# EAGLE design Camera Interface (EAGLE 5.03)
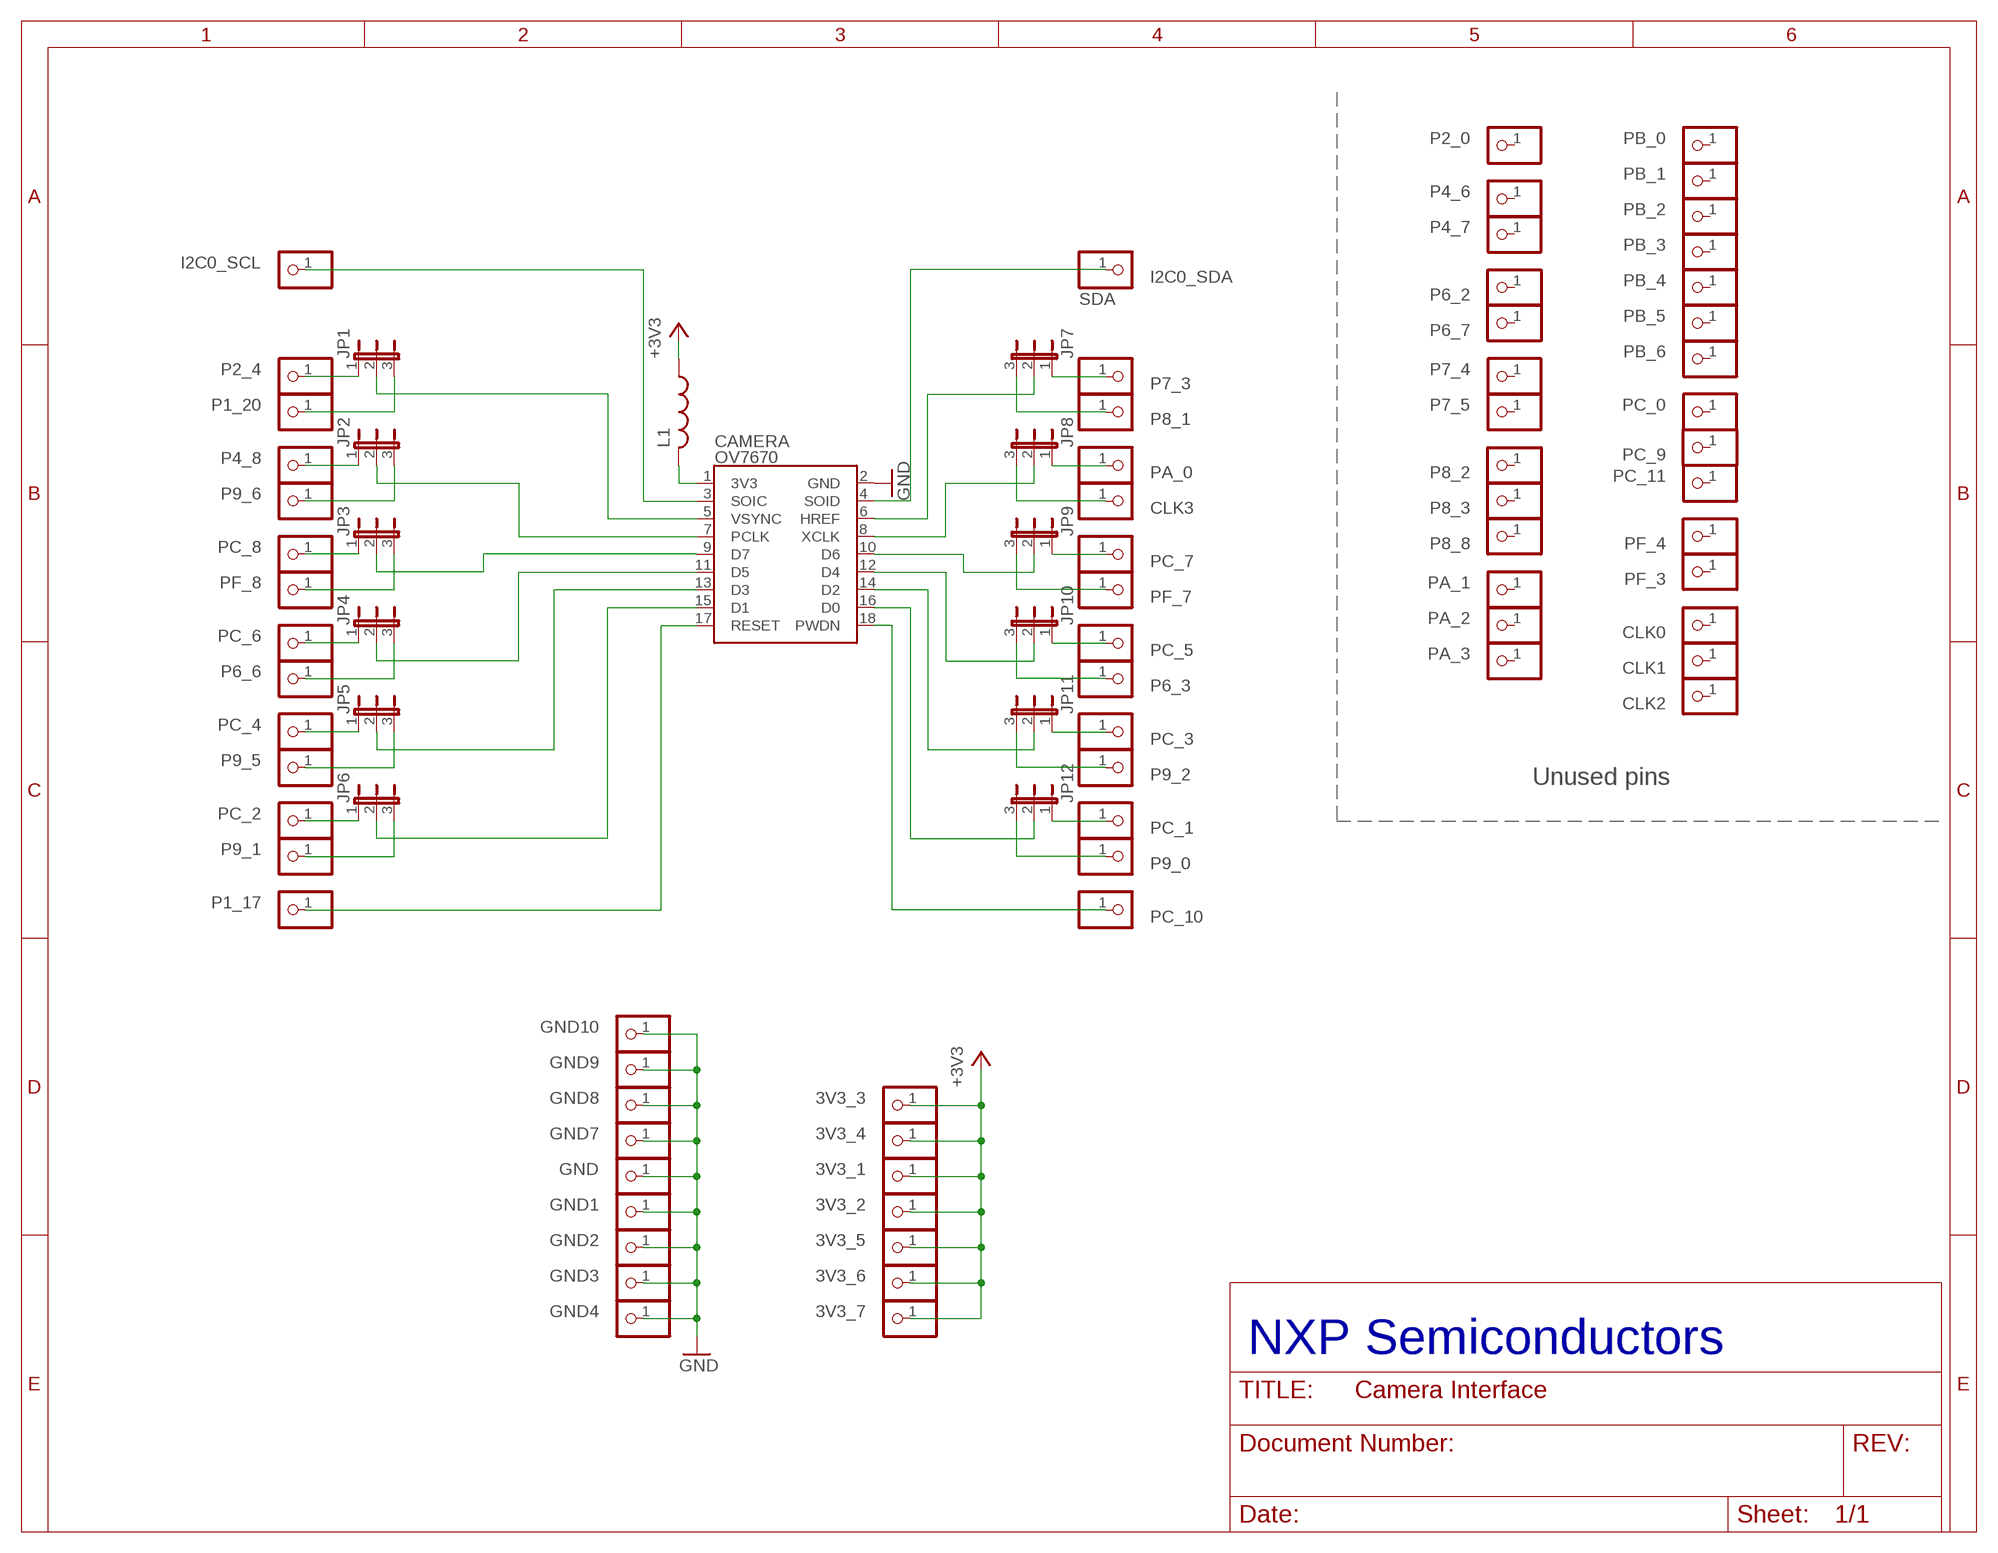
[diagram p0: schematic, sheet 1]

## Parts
3V3_1  PINHD-1X1NS  [1X01NS]
3V3_2  3V3  PINHD-1X1NS  [1X01NS]
3V3_3  3V3  PINHD-1X1NS  [1X01NS]
3V3_4  PINHD-1X1NS  [1X01NS]
3V3_5  3V3  PINHD-1X1NS  [1X01NS]
3V3_6  3V3  PINHD-1X1NS  [1X01NS]
3V3_7  3V3  PINHD-1X1NS  [1X01NS]
CAMERA  OV7670  [2X09]
CLK0  PINHD-1X1SQ  [1X1SQ]
CLK1  PINHD-1X1NS  [1X01NS]
CLK2  PINHD-1X1NS  [1X01NS]
CLK3  PINHD-1X1NS  [1X01NS]
GND  PINHD-1X1SQ  [1X1SQ]
GND1  PINHD-1X1NS  [1X01NS]
GND2  PINHD-1X1SQ  [1X1SQ]
GND3  PINHD-1X1NS  [1X01NS]
GND4  GND  PINHD-1X1NS  [1X01NS]
GND7  GND  PINHD-1X1NS  [1X01NS]
GND8  GND  PINHD-1X1NS  [1X01NS]
GND9  GND  PINHD-1X1NS  [1X01NS]
GND10  GND  PINHD-1X1NS  [1X01NS]
I2C0_SCL  PINHD-1X1NS  [1X01NS]
I2C0_SDA  SDA  PINHD-1X1NS  [1X01NS]
JP1  JP2ENS  [JP2S_NS]
JP2  JP2ENS  [JP2S_NS]
JP3  JP2ENS  [JP2S_NS]
JP4  JP2ENS  [JP2S_NS]
JP5  JP2ENS  [JP2S_NS]
JP6  JP2ENS  [JP2S_NS]
JP7  JP2ENS  [JP2S_NS]
JP8  JP2ENS  [JP2S_NS]
JP9  JP2ENS  [JP2S_NS]
JP10  JP2ENS  [JP2S_NS]
JP11  JP2ENS  [JP2S_NS]
JP12  JP2ENS  [JP2S_NS]
L1  L-USL0805  [C0805]
P1_17  PINHD-1X1NS  [1X01NS]
P1_20  PINHD-1X1NS  [1X01NS]
P2_0  PINHD-1X1NS  [1X01NS]
P2_4  PINHD-1X1NS  [1X01NS]
P4_6  PINHD-1X1NS  [1X01NS]
P4_7  PINHD-1X1NS  [1X01NS]
P4_8  PINHD-1X1NS  [1X01NS]
P6_2  PINHD-1X1NS  [1X01NS]
P6_3  PINHD-1X1NS  [1X01NS]
P6_6  PINHD-1X1NS  [1X01NS]
P6_7  PINHD-1X1NS  [1X01NS]
P7_3  PINHD-1X1NS  [1X01NS]
P7_4  PINHD-1X1NS  [1X01NS]
P7_5  PINHD-1X1NS  [1X01NS]
P8_1  PINHD-1X1NS  [1X01NS]
P8_2  PINHD-1X1NS  [1X01NS]
P8_3  PINHD-1X1NS  [1X01NS]
P8_8  PINHD-1X1NS  [1X01NS]
P9_0  PINHD-1X1SQ  [1X1SQ]
P9_1  PINHD-1X1NS  [1X01NS]
P9_2  PINHD-1X1NS  [1X01NS]
P9_5  PINHD-1X1NS  [1X01NS]
P9_6  PINHD-1X1NS  [1X01NS]
PA_0  PINHD-1X1SQ  [1X1SQ]
PA_1  PINHD-1X1NS  [1X01NS]
PA_2  PINHD-1X1NS  [1X01NS]
PA_3  PINHD-1X1NS  [1X01NS]
PB_0  PINHD-1X1SQ  [1X1SQ]
PB_1  PINHD-1X1NS  [1X01NS]
PB_2  PINHD-1X1NS  [1X01NS]
PB_3  PINHD-1X1NS  [1X01NS]
PB_4  PINHD-1X1NS  [1X01NS]
PB_5  PINHD-1X1NS  [1X01NS]
PB_6  PINHD-1X1NS  [1X01NS]
PC_0  PINHD-1X1SQ  [1X1SQ]
PC_1  PINHD-1X1NS  [1X01NS]
PC_2  PINHD-1X1NS  [1X01NS]
PC_3  PINHD-1X1NS  [1X01NS]
PC_4  PINHD-1X1NS  [1X01NS]
PC_5  PINHD-1X1NS  [1X01NS]
PC_6  PINHD-1X1NS  [1X01NS]
PC_7  PINHD-1X1NS  [1X01NS]
PC_8  PINHD-1X1NS  [1X01NS]
PC_9  PINHD-1X1NS  [1X01NS]
PC_10  PINHD-1X1NS  [1X01NS]
PC_11  PINHD-1X1NS  [1X01NS]
PF_3  PINHD-1X1NS  [1X01NS]
PF_4  PINHD-1X1NS  [1X01NS]
PF_7  PINHD-1X1NS  [1X01NS]
PF_8  PINHD-1X1NS  [1X01NS]

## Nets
+3V3: 3V3_1.1 3V3_2.1 3V3_3.1 3V3_4.1 3V3_5.1 3V3_6.1 3V3_7.1 L1.1
D0: CAMERA.16(D0) JP12.2
D1: CAMERA.15(D1) JP6.2
D2: CAMERA.14(D2) JP11.2
D3: CAMERA.13(D3) JP5.2
D4: CAMERA.12(D4) JP10.2
D5: CAMERA.11(D5) JP4.2
D6: CAMERA.10(D6) JP9.2
D7: CAMERA.9(D7) JP3.2
GND: CAMERA.2(GND) GND1.1 GND2.1 GND3.1 GND4.1 GND7.1 GND8.1 GND9.1 GND10.1 GND.1
HREF: CAMERA.6(HREF) JP7.2
N$3: JP1.1 P2_4.1
N$4: JP7.1 P7_3.1
N$6: JP8.1 PA_0.1
N$7: JP3.1 PC_8.1
N$8: JP9.1 PC_7.1
N$10: JP10.1 PC_5.1
N$12: JP11.1 PC_3.1
N$14: JP12.1 PC_1.1
N$17: JP1.3 P1_20.1
N$19: JP2.1 P4_8.1
N$20: JP2.3 P9_6.1
N$21: JP3.3 PF_8.1
N$23: JP4.1 PC_6.1
N$24: JP4.3 P6_6.1
N$25: JP5.1 PC_4.1
N$26: JP5.3 P9_5.1
N$27: JP6.1 PC_2.1
N$28: JP6.3 P9_1.1
N$29: JP7.3 P8_1.1
N$30: CLK3.1 JP8.3
N$31: JP9.3 PF_7.1
N$32: JP10.3 P6_3.1
N$33: JP11.3 P9_2.1
N$34: JP12.3 P9_0.1
N$41: CAMERA.1(3V3) L1.2
PCLK: CAMERA.7(PCLK) JP2.2
PWDN: CAMERA.18(PWDN) PC_10.1
RESET: CAMERA.17(RESET) P1_17.1
SCL: CAMERA.3(SOIC) I2C0_SCL.1
SDA: CAMERA.4(SOID) I2C0_SDA.1
VSYNC: CAMERA.5(VSYNC) JP1.2
XCLK: CAMERA.8(XCLK) JP8.2
Unconnected: CLK0.1 CLK1.1 CLK2.1 P2_0.1 P4_6.1 P4_7.1 P6_2.1 P6_7.1 P7_4.1 P7_5.1 P8_2.1 P8_3.1 P8_8.1 PA_1.1 PA_2.1 PA_3.1 PB_0.1 PB_1.1 PB_2.1 PB_3.1 PB_4.1 PB_5.1 PB_6.1 PC_0.1 PC_9.1 PC_11.1 PF_3.1 PF_4.1

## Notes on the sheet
- Unused pins
- NXP Semiconductors

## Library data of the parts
3V3_1-3V3_7 CLK0 CLK1-CLK3 GND GND1-GND4 GND7-GND10 I2C0_SCL I2C0_SDA P1_17 P1_20 P2_0 P2_4 P4_6-P4_8 P6_2 P6_3 P6_6 P6_7 P7_3-P7_5 P8_1-P8_3 P8_8 P9_0 P9_1 P9_2 P9_5 P9_6 PA_0 PA_1-PA_3 PB_0 PB_1-PB_6 PC_0 PC_1-PC_11 PF_3 PF_4 PF_7 PF_8 = pinhead:PINHD-1X1: PIN HEADER
CAMERA = Camera_Interface:OV7670
JP1-JP12 = jumper:JP2E: JUMPER
L1 = rcl:L-US: INDUCTOR, American symbol

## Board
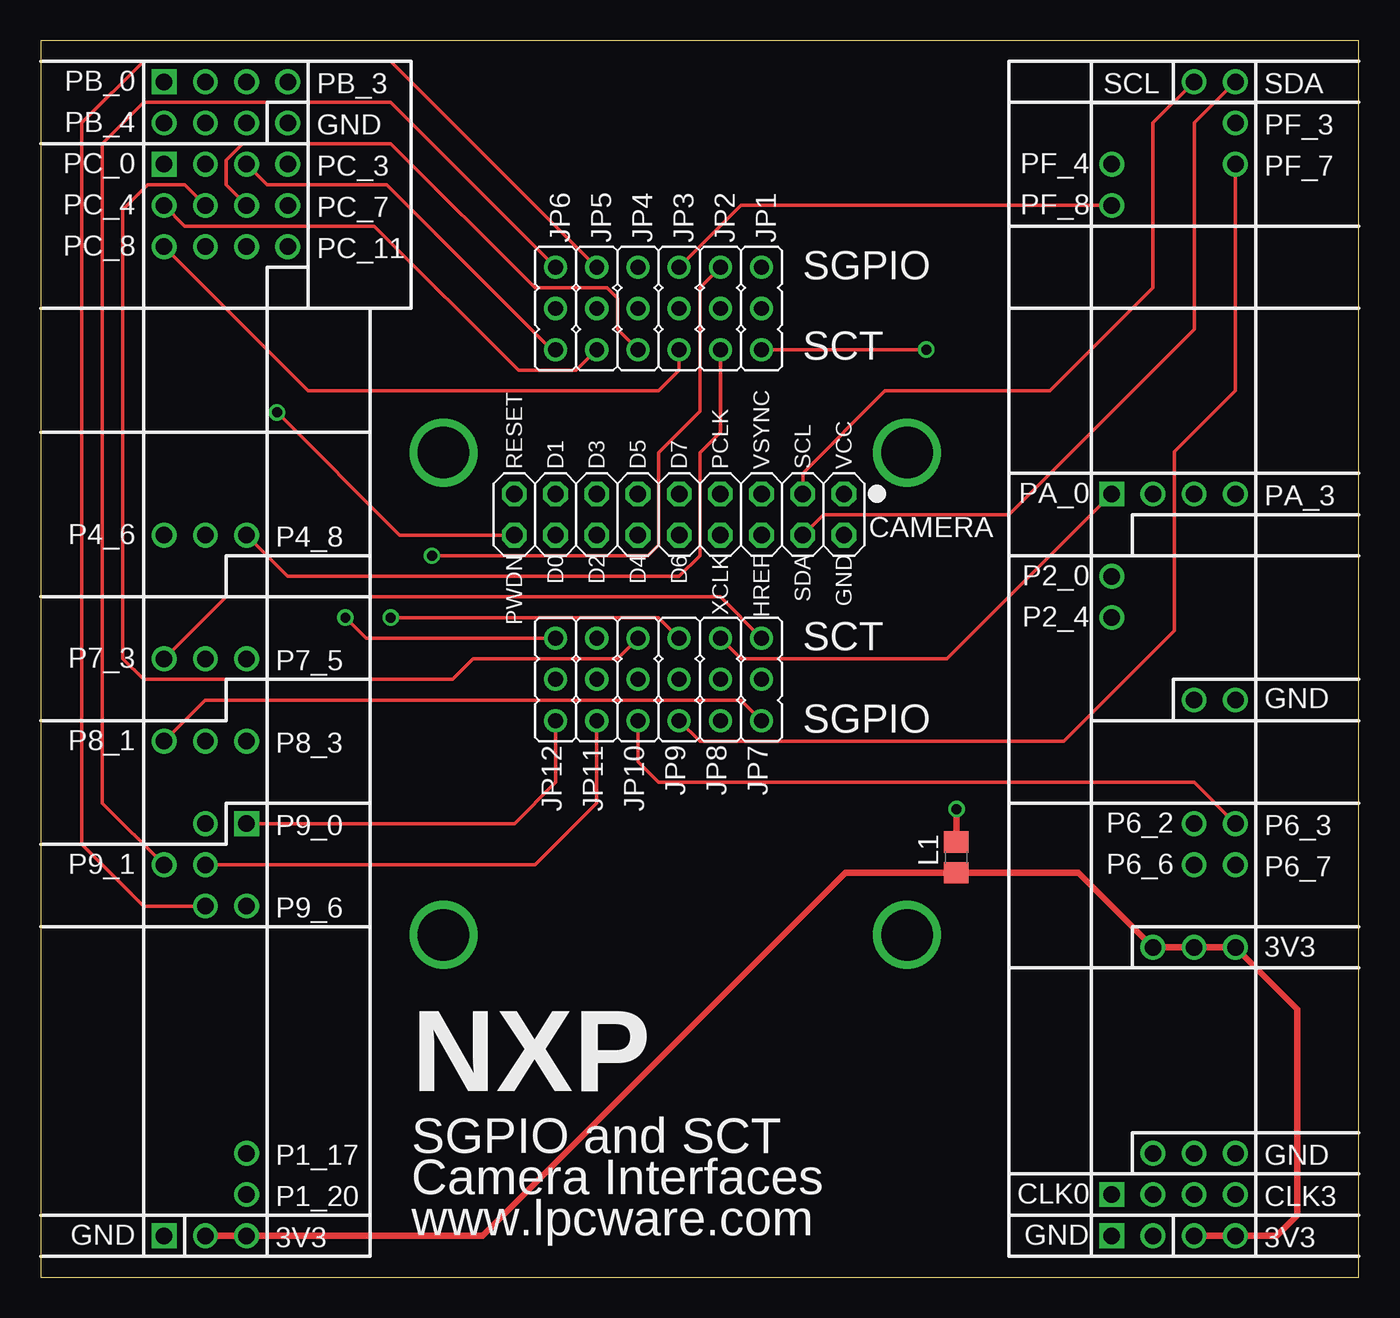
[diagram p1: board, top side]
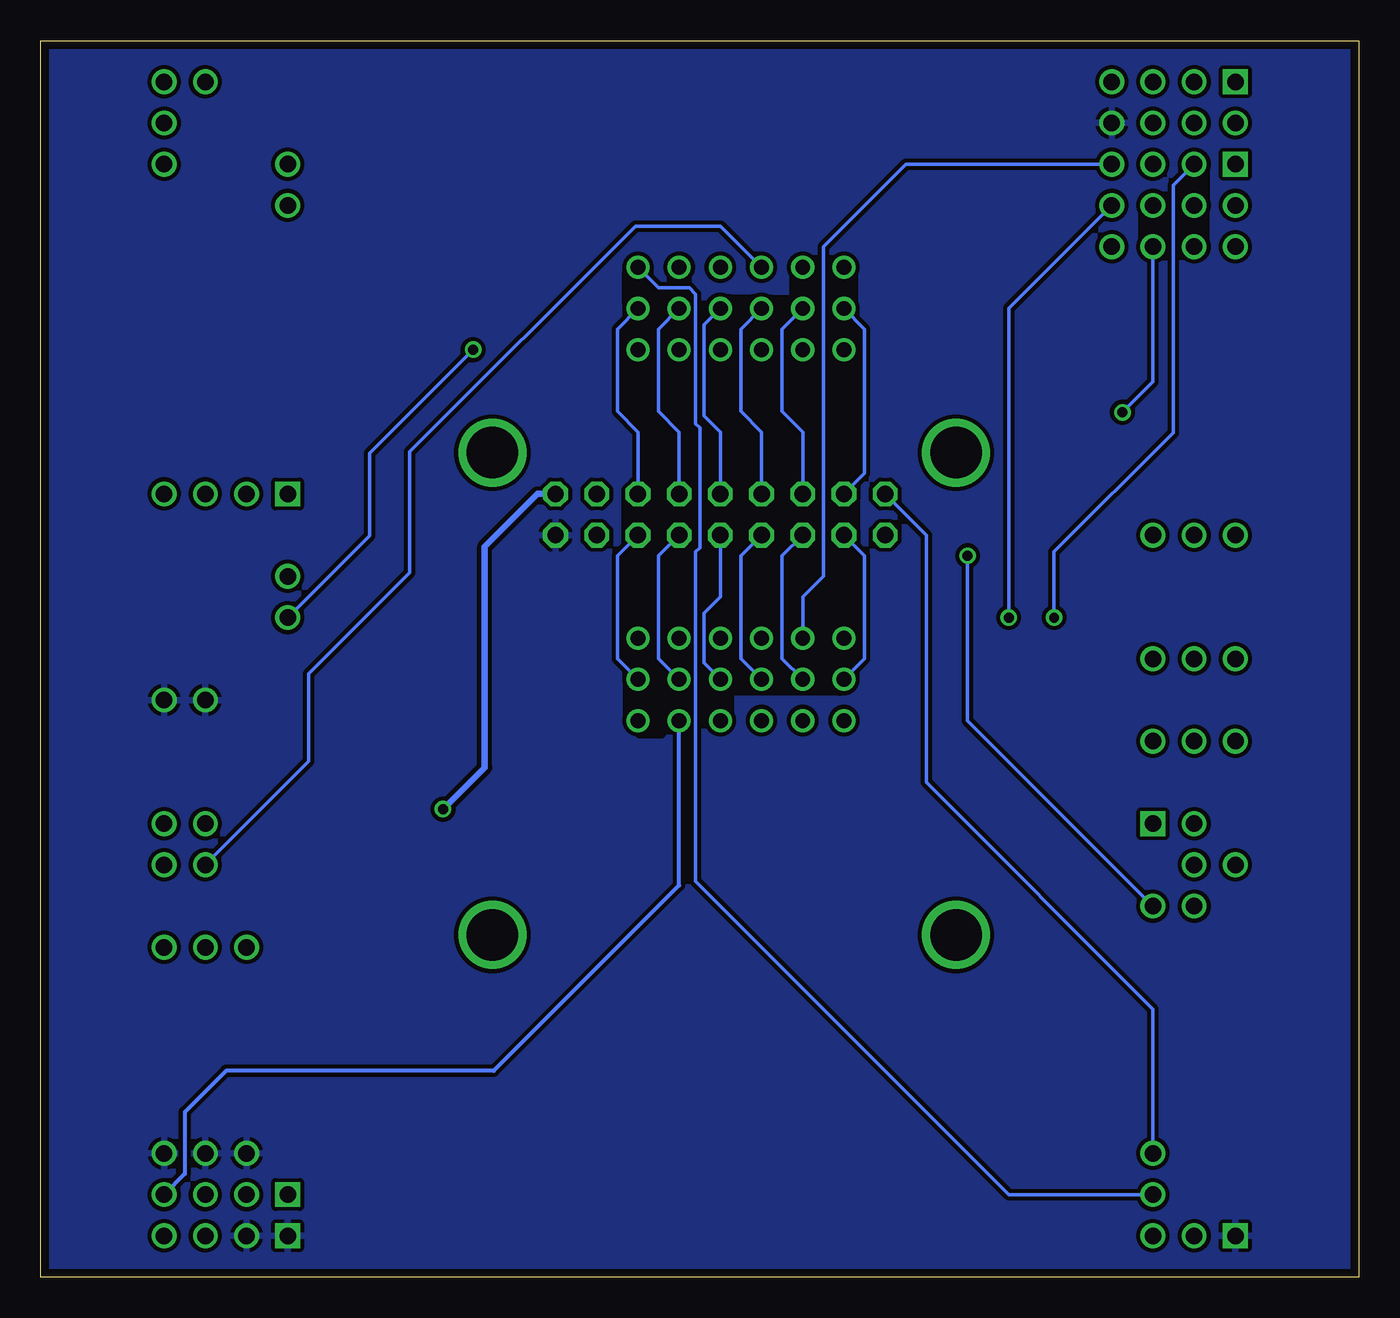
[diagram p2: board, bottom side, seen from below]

Size 81.28 x 76.2 mm. Coordinates in mm from the lower left corner, seen from the top.
Outline: 0,0 81.28,0 81.28,76.2 0,76.2 0,0
Copper layers (1*16): Top 0.035mm / dielectric 1.5mm / Bottom 0.035mm
Design rules "default *": minimum track width 8mil, minimum drill 24mil, track to track 8mil, track to pad 8mil, pad to pad 8mil, via to via 8mil, smd to smd 8mil, copper to edge 20mil, drill to drill 8mil, minimum pad ring 10mil, minimum via ring 8mil, stop-mask expansion 4mil, vias tented up to drill 0mil, thermal gap 10mil
bRestrict: area 45.1,60.1 to 45.2,61.9; area 45.2,46.2 to 45.2,47.8; area 34.9,60.2 to 36.3,60.3; area 37.4,60.2 to 38.8,60.3; area 9.5,64 to 9.6,65.4; area 9.4,66.6 to 9.5,68; area 13.3,64.1 to 13.4,65.5; area 34.8,60.3 to 34.9,61.7; area 31.1,60.2 to 31.2,61.6; area 45.1,34.8 to 45.1,36.2; area 38.8,34.8 to 38.8,36.2; area 32,36.1 to 38.7,36.1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

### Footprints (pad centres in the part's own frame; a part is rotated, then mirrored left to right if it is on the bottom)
1X01NS = drill 1.016 round: 1 0,0
2X09 = drill 1.016 octagon: 1 -10.16,-1.27; 2 -10.16,1.27; 3 -7.62,-1.27; 4 -7.62,1.27; 5 -5.08,-1.27; 6 -5.08,1.27; 7 -2.54,-1.27; 8 -2.54,1.27; 9 0,-1.27; 10 0,1.27; 11 2.54,-1.27; 12 2.54,1.27; 13 5.08,-1.27; 14 5.08,1.27; 15 7.62,-1.27; 16 7.62,1.27; 17 10.16,-1.27; 18 10.16,1.27
1X1SQ = drill 1.016 square: 1 0,0
JP2S_NS = drill 0.914 round: 1 -2.54,0; 2 0,0; 3 2.54,0
C0805 = smd 1.3 x 1.5: 1 -0.95,0; 2 0.95,0

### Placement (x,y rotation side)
3V3_1  10.16,2.54 0 top
3V3_2  12.7,2.54 0 top
3V3_3  73.66,2.54 0 top
3V3_4  71.12,2.54 0 top
3V3_5  68.58,20.32 0 top
3V3_6  71.12,20.32 0 top
3V3_7  73.66,20.32 0 top
CAMERA  39.37,46.99 180 top
CLK0  66.04,5.08 0 top
CLK1  68.58,5.08 0 top
CLK2  71.12,5.08 0 top
CLK3  73.66,5.08 0 top
GND  7.62,2.54 0 top
GND1  68.58,2.54 0 top
GND2  66.04,2.54 0 top
GND3  73.66,7.62 0 top
GND4  15.24,71.12 0 top
GND7  68.58,7.62 0 top
GND8  71.12,7.62 0 top
GND9  71.12,35.56 0 top
GND10  73.66,35.56 0 top
I2C0_SCL  71.12,73.66 90 top
I2C0_SDA  73.66,73.66 90 top
JP1  44.45,59.69 90 top
JP2  41.91,59.69 90 top
JP3  39.37,59.69 90 top
JP4  36.83,59.69 90 top
JP5  34.29,59.69 90 top
JP6  31.75,59.69 90 top
JP7  44.45,36.83 270 top
JP8  41.91,36.83 270 top
JP9  39.37,36.83 270 top
JP10  36.83,36.83 270 top
JP11  34.29,36.83 270 top
JP12  31.75,36.83 270 top
L1  56.44,25.86 90 top
P1_17  12.7,7.62 0 top
P1_20  12.7,5.08 0 top
P2_0  66.04,43.18 0 top
P2_4  66.04,40.64 0 top
P4_6  7.62,45.72 0 top
P4_7  10.16,45.72 0 top
P4_8  12.7,45.72 0 top
P6_2  71.12,27.94 0 top
P6_3  73.66,27.94 0 top
P6_6  71.12,25.4 0 top
P6_7  73.66,25.4 0 top
P7_3  7.62,38.1 0 top
P7_4  10.16,38.1 0 top
P7_5  12.7,38.1 0 top
P8_1  7.62,33.02 0 top
P8_2  10.16,33.02 0 top
P8_3  12.7,33.02 0 top
P8_8  10.16,27.94 0 top
P9_0  12.7,27.94 0 top
P9_1  7.62,25.4 0 top
P9_2  10.16,25.4 0 top
P9_5  10.16,22.86 0 top
P9_6  12.7,22.86 0 top
PA_0  66.04,48.26 0 top
PA_1  68.58,48.26 0 top
PA_2  71.12,48.26 0 top
PA_3  73.66,48.26 0 top
PB_0  7.62,73.66 90 top
PB_1  10.16,73.66 90 top
PB_2  12.7,73.66 90 top
PB_3  15.24,73.66 90 top
PB_4  7.62,71.12 180 top
PB_5  10.16,71.12 0 top
PB_6  12.7,71.12 0 top
PC_0  7.62,68.58 180 top
PC_1  10.16,68.58 0 top
PC_2  12.7,68.58 0 top
PC_3  15.24,68.58 0 top
PC_4  7.62,66.04 0 top
PC_5  10.16,66.04 0 top
PC_6  12.7,66.04 0 top
PC_7  15.24,66.04 0 top
PC_8  7.62,63.5 0 top
PC_9  10.16,63.5 0 top
PC_10  12.7,63.5 0 top
PC_11  15.24,63.5 0 top
PF_3  73.66,71.12 0 top
PF_4  66.04,68.58 0 top
PF_7  73.66,68.58 0 top
PF_8  66.04,66.04 0 top

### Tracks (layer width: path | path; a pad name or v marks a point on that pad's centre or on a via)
+3V3
  Top 0.406: 3V3_4.1 3V3_3.1 76.2,2.54 77.47,3.81 77.47,16.51 3V3_7.1 3V3_6.1 3V3_5.1 63.99,24.91 L1.1 49.62,24.91 27.25,2.54 3V3_2.1 3V3_1.1
D0
  Bottom 0.203: JP12.2 30.48,38.1 30.48,44.45 CAMERA.16
D1
  Bottom 0.203: CAMERA.15 30.48,49.53 30.48,58.42 JP6.2
D2
  Bottom 0.203: CAMERA.14 35.56,44.45 35.56,38.1 JP11.2
D3
  Bottom 0.203: CAMERA.13 34.29,52.07 35.56,53.34 35.56,58.42 JP5.2
D4
  Bottom 0.203: CAMERA.12 38.1,44.45 38.1,38.1 JP10.2
D5
  Bottom 0.203: CAMERA.11 36.83,52.07 38.1,53.34 38.1,58.42 JP4.2
D6
  Bottom 0.203: JP9.2 40.39,37.85 40.39,40.89 39.37,41.91 CAMERA.10
D7
  Bottom 0.203: JP3.2 40.39,58.67 40.39,53.09 39.37,52.07 CAMERA.9
GND
  pour Bottom (isolate 0.254): 0,0 81.28,0 81.28,76.4 0,76.4
HREF
  Bottom 0.203: CAMERA.6 45.72,44.45 45.72,38.1 JP7.2
N$3  (via drill 0.61)
  Top 0.203: JP1.1 v54.61,57.15
  Bottom 0.203: P2_4.1 60.98,45.7 60.98,50.77 v54.61,57.15
N$4
  Top 0.203: P7_3.1 11.43,41.91 41.91,41.91 JP7.1
N$6
  Top 0.203: JP8.1 43.18,38.1 55.88,38.1 PA_0.1
N$7
  Top 0.203: PC_8.1 16.51,54.61 38.1,54.61 39.37,55.88 JP3.1
N$8  (via drill 0.61)
  Top 0.203: v21.59,40.64 38.1,40.64 JP9.1
  Bottom 0.203: PC_7.1 21.59,59.69 v21.59,40.64
N$10
  Top 0.203: JP10.1 35.56,38.1 26.67,38.1 25.4,36.83 6.35,36.83 5.08,38.1 5.08,65.79 6.6,67.31 8.89,67.31 PC_5.1
N$12
  Bottom 0.203: JP11.1 34.29,41.91 33.02,43.18 33.02,63.5 27.94,68.58 PC_3.1
N$14  (via drill 0.61)
  Top 0.203: JP12.1 20.07,39.37 v18.8,40.64
  Bottom 0.203: v18.8,40.64 18.8,44.7 11.46,52.05 11.46,67.28 PC_1.1
N$17
  Bottom 0.203: JP1.3 43.18,60.96 41.27,60.96 40.89,60.58 40.89,52.58 40.64,52.32 40.64,44.96 40.89,44.7 40.89,24.38 21.59,5.08 P1_20.1
N$19
  Top 0.203: JP2.1 41.91,52.07 40.64,50.8 40.64,44.45 39.37,43.18 15.24,43.18 P4_8.1
N$20  (via drill 0.61)
  Top 0.203: JP2.3 40.64,60.96 40.64,53.34 38.1,50.8 38.1,45.09 37.47,44.45 v24.13,44.45
  Bottom 0.203: v24.13,44.45 24.13,34.29 P9_6.1
N$21
  Top 0.203: PF_8.1 43.18,66.04 JP3.3
N$23
  Top 0.203: JP4.1 35.56,58.42 35.56,60.33 34.92,60.96 30.48,60.96 21.59,69.85 12.45,69.85 11.43,68.83 11.43,67.31 PC_6.1
N$24
  Bottom 0.203: JP4.3 39.37,64.77 44.6,64.77 58.52,50.85 58.52,43.41 64.75,37.19 64.75,31.77 P6_6.1
N$25
  Top 0.203: PC_4.1 8.89,64.77 20.57,64.77 29.46,55.88 33.02,55.88 JP5.1
N$26
  Top 0.203: P9_5.1 6.35,22.86 2.54,26.67 2.54,71.12 6.35,74.93 21.59,74.93 JP5.3
N$27
  Top 0.203: PC_2.1 13.97,67.31 21.34,67.31 31.5,57.15 JP6.1
N$28
  Top 0.203: JP6.3 21.59,72.39 6.35,72.39 3.81,69.85 3.81,29.21 P9_1.1
N$29
  Top 0.203: P8_1.1 10.16,35.56 43.18,35.56 JP7.3
N$30
  Bottom 0.254: CLK3.1 72.39,6.35 72.39,10.16 69.85,12.7 53.34,12.7 41.91,24.13 JP8.3
N$31
  Top 0.203: PF_7.1 73.66,54.61 69.9,50.85 69.9,39.83 63.09,33.02 40.64,33.02 JP9.3
N$32
  Top 0.203: P6_3.1 71.12,30.48 38.1,30.48 36.83,31.75 JP10.3
N$33
  Top 0.203: P9_2.1 30.48,25.4 34.29,29.21 JP11.3
N$34
  Top 0.203: P9_0.1 29.21,27.94 31.75,30.48 JP12.3
N$41  (via drill 0.61)
  Top 0.406: L1.2 56.46,26.83 v56.46,28.83
  Bottom 0.406: CAMERA.1 50.65,48.26 53.9,45.01 53.9,31.39 v56.46,28.83
N$42  (via drill 3.17)
  other vias: 53.42,50.8
N$43  (via drill 3.17)
  other vias: 53.42,21.08
N$44  (via drill 3.17)
  other vias: 24.85,21.08
N$45  (via drill 3.17)
  other vias: 24.85,50.8
PCLK
  Bottom 0.203: JP2.2 43.18,58.42 43.18,53.34 41.91,52.07 CAMERA.7
PWDN  (via drill 0.61)
  Top 0.203: CAMERA.18 22.15,45.72 v14.58,53.29
  Bottom 0.203: PC_10.1 12.7,55.17 v14.58,53.29
RESET
  Bottom 0.203: CAMERA.17 26.67,45.72 26.67,30.48 12.7,16.51 P1_17.1
SCL
  Top 0.203: I2C0_SCL.1 68.58,71.12 68.58,60.96 62.23,54.61 52.07,54.61 46.99,49.53 CAMERA.3
SDA
  Top 0.203: CAMERA.4 48.26,46.99 59.69,46.99 71.12,58.42 71.12,71.12 I2C0_SDA.1
VSYNC
  Bottom 0.203: JP1.2 45.72,58.42 45.72,53.34 44.45,52.07 CAMERA.5
XCLK
  Bottom 0.203: CAMERA.8 43.18,44.45 43.18,38.1 JP8.2

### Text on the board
tPlace: SGPIO | SCT | RESET | D1 | D3 | D5 | D7 | PCLK | VSYNC | SCL | VCC | PWDN | D0 | D2 | D4 | D6 | XCLK | HREF | SDA | GND | SCT | SGPIO | NXP | SGPIO and SCT | Camera Interfaces | www.lpcware.com
tNames: SCL | SDA | GND | PF_3 | PF_4 | P2_0 | GND | P8_3 | 3V3 | GND | GND | 3V3 | 3V3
